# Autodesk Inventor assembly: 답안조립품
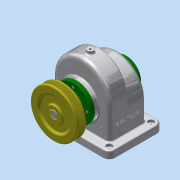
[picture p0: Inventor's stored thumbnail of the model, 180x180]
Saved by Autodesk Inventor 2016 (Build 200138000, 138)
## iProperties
Created: 2017-11
Part Number: 답안조립품
Material: 일반
Document SubType Name: Assembly
Designer: 605-12
Author: 605-12
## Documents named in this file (14)
- C:\Users\605-12\Desktop\471107V1026\답안조립품.iam
- C:\Users\605-12\Desktop\471107V1026\본체.ipt
- C:\Users\605-12\Desktop\471107V1026\뒤커버.ipt
- C:\Users\605-12\Desktop\471107V1026\볼트 M3 x 8.ipt
- C:\Users\605-12\Desktop\471107V1026\베어링 6002.ipt
- C:\Users\605-12\Desktop\471107V1026\축.ipt
- C:\Users\605-12\Desktop\471107V1026\키 - 6 x 6 x 22.ipt
- C:\Users\605-12\Desktop\471107V1026\키 - 5 x 5 x 18.ipt
- C:\Users\605-12\Desktop\471107V1026\스퍼기어.ipt
- C:\Users\605-12\Desktop\471107V1026\앞커버.ipt
- C:\Users\605-12\Desktop\471107V1026\오일 실 15 30 7.ipt
- C:\Users\605-12\Desktop\471107V1026\V-벨트풀리.ipt
- C:\Users\605-12\Desktop\471107V1026\멈춤나사 - M4 x 10.ipt
- 멈춤나사 - M4 x 10.ipt
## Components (1 placed, 1 different names)
1. V-벨트풀리:1 — 각도:4
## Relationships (1: Angle 1)
- 각도:4 [Angle]: V-벨트풀리:1
